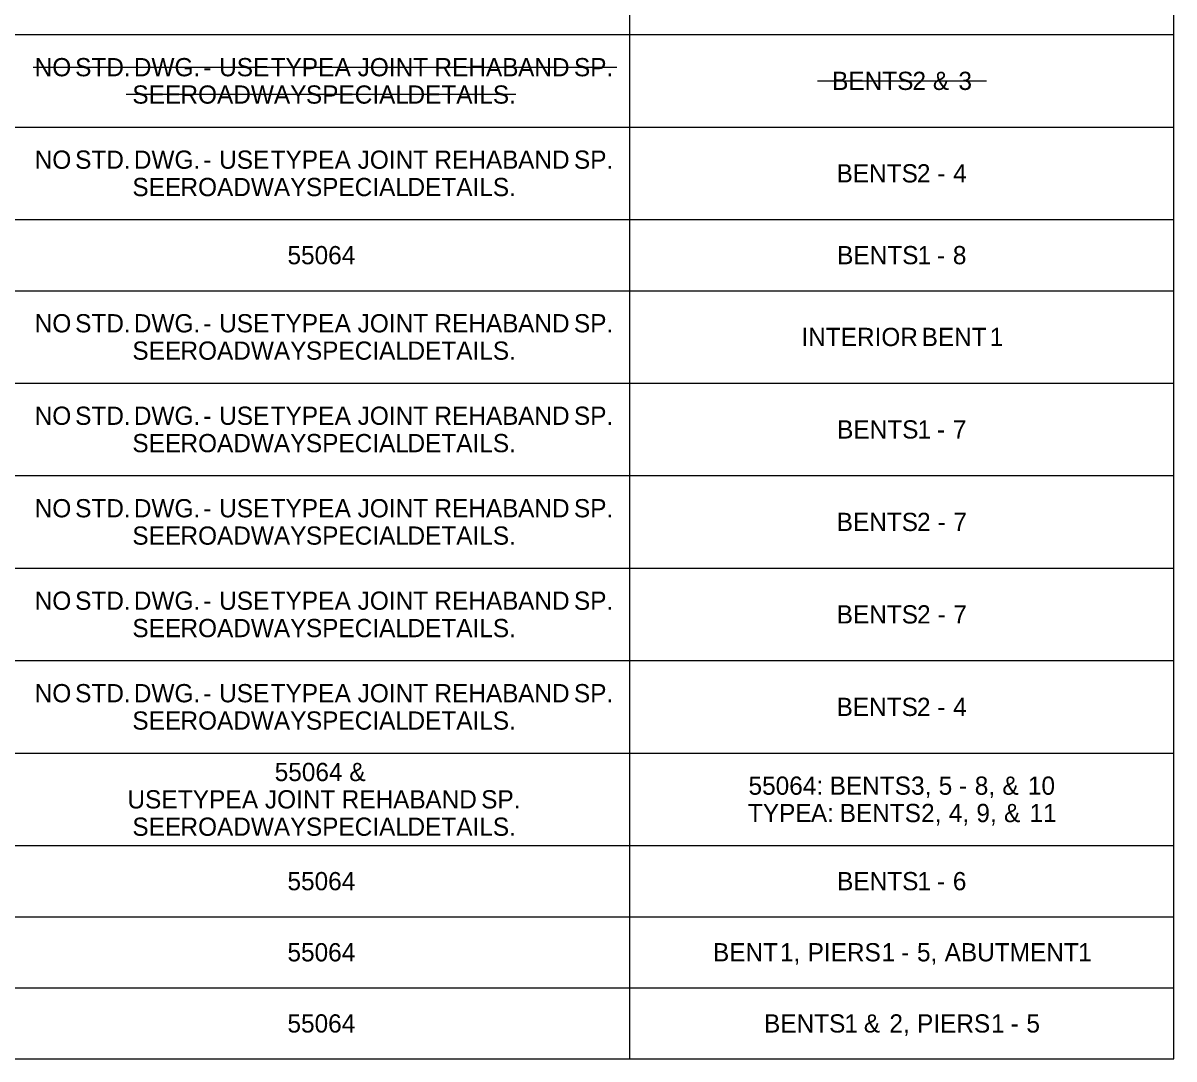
# Model space of a CAD drawing. Extents: x 18 to 14744716, y -5 to 1829144.
# Drawn here: x 39.14 to 47.01, y -1.61 to 5.47 of the extents above; entities that cross this region are included whole.
import ezdxf

# ---------------------------------------------------------------- set-up
doc = ezdxf.new("R2010")
doc.units = 0
doc.layers.add('B_Dimensions', color=7, linetype='Continuous')
doc.layers.add('B_Text', color=7, linetype='Continuous')

msp = doc.modelspace()

# ---------------------------------------------------------------- linework, layer by layer
at = {"layer": 'B_Dimensions'}
for p, q in [((39.2064, 5.1724), (43.2008, 5.1724)), ((44.573, 5.0788), (45.731, 5.0788)), ((42.5087, 4.9852), (39.8419, 4.9852))]:
    msp.add_line(p, q, dxfattribs=at)
at = {"layer": 'B_Text'}
for p, q in [((43.2896, -1.6136), (43.2896, 14.8497)), ((47.013, -1.6136), (47.013, 14.8497)), ((24.3562, 5.3952), (47.013, 5.3952)), ((23.2002, 4.7624), (47.013, 4.7624)), ((24.3562, 4.1297), (47.013, 4.1297)), ((23.2002, 3.643), (47.013, 3.643)), ((23.2002, 3.0102), (47.013, 3.0102)), ((24.3562, 2.3775), (47.013, 2.3775)), ((24.3562, 1.7448), (47.013, 1.7448)), ((23.2002, 1.112), (47.013, 1.112)), ((24.3562, 0.4793), (47.013, 0.4793)), ((23.2002, -0.1535), (47.013, -0.1535)), ((24.3562, -0.6402), (47.013, -0.6402)), ((24.3562, -1.1269), (47.013, -1.1269)), ((23.2002, -1.6136), (47.013, -1.6136))]:
    msp.add_line(p, q, dxfattribs=at)

# ---------------------------------------------------------------- texts
for s, p in [('NO', (39.2166, 5.11)), (' STD.', (39.4471, 5.11)), (' DWG.', (39.8488, 5.11)), (' USE', (40.4325, 5.11)), (' TYPE', (40.7849, 5.11)), (' A', (41.223, 5.11)), (' JOINT', (41.3804, 5.11)), (' REHAB', (41.9058, 5.11)), (' AND', (42.4783, 5.11)), (' SP.', (42.8605, 5.11)), (' -', (40.324, 5.11)), ('BENTS', (44.6736, 5.0164)), (' 2', (45.1771, 5.0164)), (' &', (45.3168, 5.0164)), (' 3', (45.4914, 5.0164)), ('SEE', (39.8851, 4.9228)), (' ROADWAY', (40.1677, 4.9228)), (' SPECIAL', (41.0263, 4.9228)), (' DETAILS.', (41.7214, 4.9228)), ('NO', (39.2166, 4.4772)), (' STD.', (39.4471, 4.4772)), (' DWG.', (39.8488, 4.4772)), (' USE', (40.4325, 4.4772)), (' TYPE', (40.7849, 4.4772)), (' A', (41.223, 4.4772)), (' JOINT', (41.3804, 4.4772)), (' REHAB', (41.9058, 4.4772)), (' AND', (42.4783, 4.4772)), (' SP.', (42.8605, 4.4772)), (' -', (40.324, 4.4772)), ('BENTS', (44.704, 4.3836)), (' 2', (45.2075, 4.3836)), (' 4', (45.4556, 4.3836)), ('SEE', (39.8851, 4.29)), (' ROADWAY', (40.1677, 4.29)), (' SPECIAL', (41.0263, 4.29)), (' DETAILS.', (41.7214, 4.29)), (' -', (45.3472, 4.3836)), ('55064', (40.9464, 3.8239)), ('BENTS', (44.708, 3.8239)), (' 1', (45.2116, 3.8239)), (' 8', (45.4534, 3.8239)), (' -', (45.345, 3.8239)), ('NO', (39.2166, 3.3578)), (' STD.', (39.4471, 3.3578)), (' DWG.', (39.8488, 3.3578)), (' USE', (40.4325, 3.3578)), (' TYPE', (40.7849, 3.3578)), (' A', (41.223, 3.3578)), (' JOINT', (41.3804, 3.3578)), (' REHAB', (41.9058, 3.3578)), (' AND', (42.4783, 3.3578)), (' SP.', (42.8605, 3.3578)), (' -', (40.324, 3.3578)), ('INTERIOR', (44.4635, 3.2642)), (' BENT', (45.2398, 3.2642)), (' 1', (45.7056, 3.2642)), ('SEE', (39.8851, 3.1706)), (' ROADWAY', (40.1677, 3.1706)), (' SPECIAL', (41.0263, 3.1706)), (' DETAILS.', (41.7214, 3.1706)), ('NO', (39.2166, 2.7251)), (' STD.', (39.4471, 2.7251)), (' DWG.', (39.8488, 2.7251)), (' USE', (40.4325, 2.7251)), (' TYPE', (40.7849, 2.7251)), (' A', (41.223, 2.7251)), (' JOINT', (41.3804, 2.7251)), (' REHAB', (41.9058, 2.7251)), (' AND', (42.4783, 2.7251)), (' SP.', (42.8605, 2.7251)), (' -', (40.324, 2.7251)), ('BENTS', (44.708, 2.6315)), (' 1', (45.2116, 2.6315)), (' -', (45.345, 2.6315)), (' 7', (45.4534, 2.6315)), ('SEE', (39.8851, 2.5379)), (' ROADWAY', (40.1677, 2.5379)), (' SPECIAL', (41.0263, 2.5379)), (' DETAILS.', (41.7214, 2.5379)), ('NO', (39.2166, 2.0923)), (' STD.', (39.4471, 2.0923)), (' DWG.', (39.8488, 2.0923)), (' USE', (40.4325, 2.0923)), (' TYPE', (40.7849, 2.0923)), (' A', (41.223, 2.0923)), (' JOINT', (41.3804, 2.0923)), (' REHAB', (41.9058, 2.0923)), (' AND', (42.4783, 2.0923)), (' SP.', (42.8605, 2.0923)), (' -', (40.324, 2.0923)), ('BENTS', (44.7049, 1.9987)), (' 2', (45.2085, 1.9987)), (' -', (45.3481, 1.9987)), (' 7', (45.4565, 1.9987)), ('SEE', (39.8851, 1.9051)), (' ROADWAY', (40.1677, 1.9051)), (' SPECIAL', (41.0263, 1.9051)), (' DETAILS.', (41.7214, 1.9051)), ('NO', (39.2166, 1.4596)), (' STD.', (39.4471, 1.4596)), (' DWG.', (39.8488, 1.4596)), (' USE', (40.4325, 1.4596)), (' TYPE', (40.7849, 1.4596)), (' A', (41.223, 1.4596)), (' JOINT', (41.3804, 1.4596)), (' REHAB', (41.9058, 1.4596)), (' AND', (42.4783, 1.4596)), (' SP.', (42.8605, 1.4596)), (' -', (40.324, 1.4596)), ('BENTS', (44.7049, 1.366)), (' 2', (45.2085, 1.366)), (' -', (45.3481, 1.366)), (' 7', (45.4565, 1.366)), ('SEE', (39.8851, 1.2724)), (' ROADWAY', (40.1677, 1.2724)), (' SPECIAL', (41.0263, 1.2724)), (' DETAILS.', (41.7214, 1.2724)), ('NO', (39.2166, 0.8268)), (' STD.', (39.4471, 0.8268)), (' DWG.', (39.8488, 0.8268)), (' USE', (40.4325, 0.8268)), (' TYPE', (40.7849, 0.8268)), (' A', (41.223, 0.8268)), (' JOINT', (41.3804, 0.8268)), (' REHAB', (41.9058, 0.8268)), (' AND', (42.4783, 0.8268)), (' SP.', (42.8605, 0.8268)), (' -', (40.324, 0.8268)), ('BENTS', (44.704, 0.7332)), (' 2', (45.2075, 0.7332)), (' -', (45.3472, 0.7332)), (' 4', (45.4556, 0.7332)), ('SEE', (39.8851, 0.6396)), (' ROADWAY', (40.1677, 0.6396)), (' SPECIAL', (41.0263, 0.6396)), (' DETAILS.', (41.7214, 0.6396)), ('55064', (40.8591, 0.2877)), (' &', (41.3231, 0.2877)), ('55064:', (44.1015, 0.1941)), (' BENTS', (44.6102, 0.1941)), (' 3,', (45.1673, 0.1941)), (' 5', (45.3564, 0.1941)), (' 8,', (45.6032, 0.1941)), (' &', (45.7923, 0.1941)), (' 10', (45.967, 0.1941)), (' -', (45.4948, 0.1941)), ('USE', (39.8513, 0.1005)), (' TYPE', (40.1502, 0.1005)), (' A', (40.5883, 0.1005)), (' JOINT', (40.7457, 0.1005)), (' REHAB', (41.2711, 0.1005)), (' AND', (41.8436, 0.1005)), (' SP.', (42.2258, 0.1005)), ('TYPE', (44.0974, 0.0069)), (' A:', (44.482, 0.0069)), (' BENTS', (44.6789, 0.0069)), (' 2,', (45.236, 0.0069)), (' 4,', (45.4251, 0.0069)), (' 9,', (45.6143, 0.0069)), (' &', (45.8034, 0.0069)), (' 11', (45.978, 0.0069)), ('SEE', (39.8851, -0.0867)), (' ROADWAY', (40.1677, -0.0867)), (' SPECIAL', (41.0263, -0.0867)), (' DETAILS.', (41.7214, -0.0867)), ('55064', (40.9464, -0.4592)), ('BENTS', (44.7078, -0.4592)), (' 1', (45.2113, -0.4592)), (' 6', (45.4532, -0.4592)), (' -', (45.3447, -0.4592)), ('55064', (40.9464, -0.9459)), ('BENT', (43.8583, -0.9459)), (' 1,', (44.2705, -0.9459)), (' PIERS', (44.4597, -0.9459)), (' 1', (44.966, -0.9459)), (' 5,', (45.2079, -0.9459)), (' ABUTMENT', (45.397, -0.9459)), (' 1', (46.3108, -0.9459)), (' -', (45.0994, -0.9459)), ('55064', (40.9464, -1.4327)), ('BENTS', (44.2076, -1.4327)), (' 1', (44.7112, -1.4327)), (' &', (44.8446, -1.4327)), (' 2,', (45.0192, -1.4327)), (' PIERS', (45.2084, -1.4327)), (' 1', (45.7147, -1.4327)), (' 5', (45.9566, -1.4327)), (' -', (45.8481, -1.4327))]:
    msp.add_text(s, height=0.1248, dxfattribs=at).set_placement(p)

doc.saveas('drawing.dxf')
